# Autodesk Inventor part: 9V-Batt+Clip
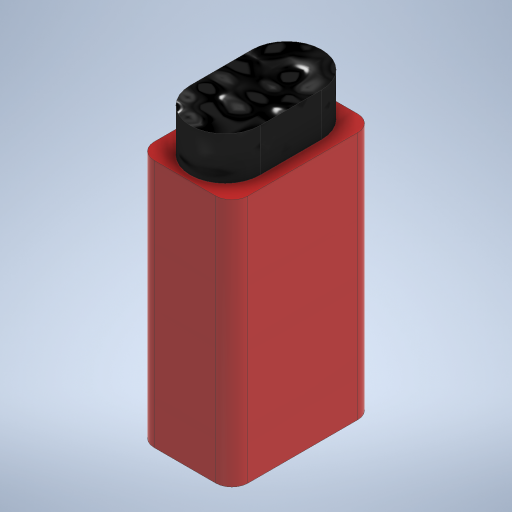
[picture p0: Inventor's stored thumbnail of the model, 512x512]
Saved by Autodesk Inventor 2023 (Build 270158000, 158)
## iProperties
Created: 2023-11
Part Number: 9V-Batt+Clip
Material: Generisch
Document SubType Name: Modeling
Designer: Admin
Density: 1 g/cm^3
Appearance: Vorgabe
Author: Admin
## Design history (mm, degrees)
sketch "Skizze1"
  geometry: L1 (5.75, 13.25)-(-5.75, 13.25); L2 (-8.75, 10.25)-(-8.75, -10.25); L3 (-5.75, -13.25)-(5.75, -13.25); L4 (8.75, -10.25)-(8.75, 10.25); L5 (8.75, 13.25)-(-8.75, -13.25); L6 (-8.75, 13.25)-(8.75, -13.25); A1 r 3 centre (5.75, 10.25) between (8.75, 10.25) and (5.75, 13.25); A2 r 3 centre (5.75, -10.25) between (5.75, -13.25) and (8.75, -10.25); A3 r 3 centre (-5.75, -10.25) between (-8.75, -10.25) and (-5.75, -13.25); A4 r 3 centre (-5.75, 10.25) between (-5.75, 13.25) and (-8.75, 10.25); 1 further point
  constraints: 12 end point, 8 point on circle, 8 point on line, 8 tangent, 4 centre point, 3 equal radius, 2 midpoint, 2 parallel, 1 horizontal, 1 perpendicular
  dimensions: "d0" = 17.5 distance of L6.end L5.end; "d1" = 26.5 distance of L5.end L6.start; "d2" = 3 radius of A1
extrude "Extrusion1" new body sketch "Skizze1" distance "d3" = 46.4; taper "d4" = 0 deg
sketch "Skizze2"
  geometry: L1 (0, -6.5)-(0, 6.5); C1 r 2.3 at (0, -6.5); C2 r 2.8 at (0, -6.5); C3 r 2.8 at (0, 6.5); C4 r 4 at (0, 6.5); 2 further points
  constraints: 4 centre point, 3 coincident, 2 end point, 1 midpoint, 1 vertical
  dimensions: "d5" = 5.6 diameter of C2; "d6" = 5.6 diameter of C3; "d7" = 8 diameter of C4; "d8" = 4.6 diameter of C1; "d9" = 13 distance of C3.centre C1.centre
extrude "Extrusion2" join sketch "Skizze2" distance "d10" = 3; taper "d11" = 0 deg
sketch "Skizze3"
  geometry: L1 (0, 5.75)-(0, -5.75); L2 (-6.5, 5.75)-(-6.5, -5.75); L3 (6.5, -5.75)-(6.5, 5.75); A1 r 6.5 centre (0, 5.75) between (6.5, 5.75) and (-6.5, 5.75); A2 r 6.5 centre (0, -5.75) between (-6.5, -5.75) and (6.5, -5.75); 2 further points
  constraints: 8 end point, 4 point on circle, 4 tangent, 2 centre point, 1 coincident, 1 midpoint, 1 parallel, 1 vertical
  dimensions: "d12" = 11.5 distance of L1.start L1.end; "d13" = 6.5 radius of A1
extrude "Extrusion3" join sketch "Skizze3" distance "d14" = 8; taper "d15" = 0 deg
node "Volumenkörper1"
